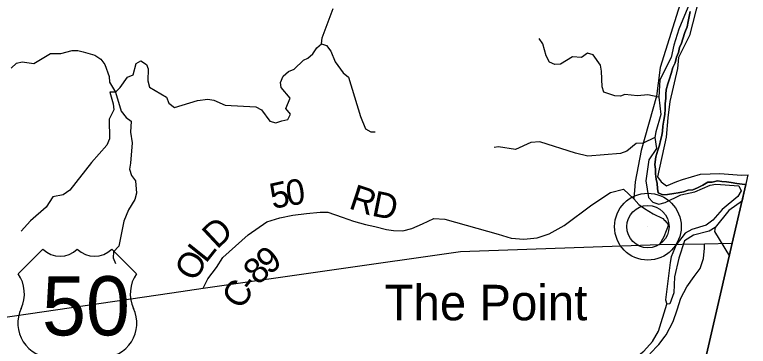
# Model space of a CAD drawing. Extents: x 1525783 to 1900577, y 218250 to 627376.
# Drawn here: x 1720827 to 1729463, y 448212 to 452113 of the extents above; entities that cross this region are included whole.
import ezdxf

# ---------------------------------------------------------------- set-up
doc = ezdxf.new("R2010")
doc.units = 0
for name, color, linetype in [('GM_X_Adjacent_County', 7, 'Continuous'), ('GM_X_County', 7, 'Continuous'), ('GM_X_County_Road', 7, 'Continuous'), ('GM_X_County_Road_Text', 7, 'Continuous'), ('GM_X_Major_Lake', 7, 'Continuous'), ('GM_X_Major_River', 7, 'Continuous'), ('GM_X_Minor_River', 7, 'Continuous'), ('GM_X_Township', 7, 'Continuous'), ('GM_X_Township_Road', 7, 'Continuous'), ('GM_X_Unincorporated', 7, 'Continuous'), ('GM_X_Unincorporated_Location', 7, 'Continuous'), ('GM_X_Unincorporated_Text', 7, 'Continuous'), ('GM_X_US_Location', 7, 'Continuous'), ('GM_X_US_Route', 7, 'Continuous'), ('GM_X_US_Shield', 7, 'Continuous')]:
    doc.layers.add(name, color=color, linetype=linetype)

msp = doc.modelspace()

# ---------------------------------------------------------------- linework, layer by layer
at = {"layer": 'GM_X_Adjacent_County'}
msp.add_lwpolyline([(1727145.2, 440204.4), (1729274, 449424.4), (1729433.6, 450116.2), (1729392, 450119.4), (1729326.2, 450126.4), (1729262.4, 450139.3), (1729206.5, 450146.2), (1729152.6, 450151), (1729098.8, 450159.8), (1729038.5, 450142.6), (1728984.6, 450143.4), (1728926, 450106.1), (1728863.6, 450075), (1728809.3, 450053.7), (1728755.2, 450050.5), (1728701, 450031.2), (1728638.8, 450018.1), (1728584.7, 450008.8), (1728510.5, 449997.9), (1728456.5, 449992.6), (1728402.9, 450017.5), (1728395.7, 450069.7), (1728390.6, 450127.9), (1728377.4, 450180.3), (1728368.3, 450240.5), (1728369.2, 450296.7), (1728362, 450350.9), (1728373.4, 450441), (1728396.6, 450518.8), (1728417.5, 450576.7), (1728430.3, 450632.6), (1728443.2, 450690.6), (1728452.1, 450744.6), (1728457, 450802.7), (1728470, 450872.7), (1728481.1, 450938.7), (1728484, 451002.8), (1728485.1, 451068.9), (1728492, 451127), (1728492.7, 451177.1), (1728497.6, 451231.2), (1728514.6, 451299.1), (1728533.5, 451359), (1728554.5, 451420.8), (1728575.6, 451492.7), (1728602.4, 451548.4), (1728619.4, 451612.3), (1728640.3, 451670.2), (1728653.1, 451726.1), (1728677.9, 451777.9), (1728692.7, 451829.8), (1728715.9, 451905.7), (1728742.9, 451971.5), (1728755.8, 452031.4), (1728766.8, 452093.4), (1728779.7, 452151.4)], dxfattribs=at)
at = {"layer": 'GM_X_County'}
msp.add_lwpolyline([(1728779.7, 452151.4), (1728766.8, 452093.4), (1728755.8, 452031.4), (1728742.9, 451971.5), (1728715.9, 451905.7), (1728692.7, 451829.8), (1728677.9, 451777.9), (1728653.1, 451726.1), (1728640.3, 451670.2), (1728619.4, 451612.3), (1728602.4, 451548.4), (1728575.6, 451492.7), (1728554.5, 451420.8), (1728533.5, 451359), (1728514.6, 451299.1), (1728497.6, 451231.2), (1728492.7, 451177.1), (1728492, 451127), (1728485.1, 451068.9), (1728484, 451002.8), (1728481.1, 450938.7), (1728470, 450872.7), (1728457, 450802.7), (1728452.1, 450744.6), (1728443.2, 450690.6), (1728430.3, 450632.6), (1728417.5, 450576.7), (1728396.6, 450518.8), (1728373.4, 450441), (1728362, 450350.9), (1728369.2, 450296.7), (1728368.3, 450240.5), (1728377.4, 450180.3), (1728390.6, 450127.9), (1728395.7, 450069.7), (1728402.9, 450017.5), (1728456.5, 449992.6), (1728510.5, 449997.9), (1728584.7, 450008.8), (1728638.8, 450018.1), (1728701, 450031.2), (1728755.2, 450050.5), (1728809.3, 450053.7), (1728863.6, 450075), (1728926, 450106.1), (1728984.6, 450143.4), (1729038.5, 450142.6), (1729098.8, 450159.8), (1729152.6, 450151), (1729206.5, 450146.2), (1729262.4, 450139.3), (1729326.2, 450126.4), (1729392, 450119.4), (1729433.6, 450116.2), (1729274, 449424.4), (1727145.2, 440204.4)], dxfattribs=at)
at = {"layer": 'GM_X_County_Road'}
for points in [[(1723046.4, 448894.6), (1723101.1, 449007), (1723204, 449139.7), (1723276.5, 449256.8), (1723576.5, 449524.3), (1723794.1, 449676.9), (1723947.4, 449724.2), (1724102.4, 449755.4), (1724261.2, 449774.5), (1724424, 449789.6), (1724512.3, 449791.9), (1724683.6, 449732.5), (1724817, 449683.8), (1724954.7, 449647.1), (1725066.4, 449620.9), (1725202.1, 449586.2), (1725286.1, 449574.6), (1725394.4, 449570.6), (1725503.1, 449596.6), (1725626.6, 449652.5), (1725762.1, 449714.3), (1725892.4, 449709.8), (1726518.6, 449531.4), (1726672.2, 449486.3), (1726822.3, 449473.5), (1726979, 449486.6), (1727118.3, 449534.2), (1727296.7, 449635.3), (1727620.3, 449878.2), (1727841.8, 450022.7), (1727992.9, 450060), (1728115, 449947.3), (1728173.9, 449881.9), (1728239.1, 449834.5), (1728342.1, 449770.3), (1728457.4, 449715.9), (1728477.8, 449692), (1728478.7, 449691.1)], [(1728478.7, 449691.1), (1728522.1, 449640.3), (1728467.2, 449498.8), (1728418, 449410.4)]]:
    msp.add_lwpolyline(points, dxfattribs=at)
at = {"layer": 'GM_X_Major_Lake'}
msp.add_lwpolyline([(1720787.2, 451484.9), (1720850.2, 451542.3), (1720916.5, 451557.5), (1721052.5, 451539.7), (1721250.6, 451657.6), (1721368.8, 451656.1), (1721503.6, 451692.5), (1721569.7, 451693.7), (1721633.6, 451674.8), (1721769.3, 451637), (1721840.8, 451592), (1721890, 451527.2), (1721938.2, 451388.2), (1721945.2, 451319.9), (1722013.7, 451202.7), (1722070.6, 451256.1), (1722156.5, 451379.4), (1722223, 451404.6), (1722256.9, 451540.6), (1722313.5, 451572), (1722377, 451529), (1722398.3, 451476.6), (1722396.3, 451336.3), (1722415.3, 451261.8), (1722614.1, 451143), (1722643.1, 451072.4), (1722708.6, 451023.4), (1722980.2, 451104.3), (1723100.7, 451120.8), (1723170.7, 451107.9), (1723306.1, 451050), (1723666.6, 451031.4), (1723734.2, 450992.5), (1723830.5, 450860.9), (1723900.3, 450840), (1723970.8, 450863.1), (1724041.2, 450882.3), (1724074.1, 450942), (1724017, 451009), (1724068.8, 451132.7), (1723964.3, 451256.3), (1723955.2, 451316.6), (1723986.2, 451388.4), (1724051.2, 451445.8), (1724115.6, 451471), (1724227.4, 451577.9), (1724277.8, 451601.4), (1724338.6, 451652.8), (1724383.7, 451722.4), (1724438.5, 451771.8), (1724445.5, 451839.9), (1724576.6, 452185.3)], dxfattribs=at)
at = {"layer": 'GM_X_Major_River'}
msp.add_line((1729392.4, 449923.8), (1729462.9, 450229.2), dxfattribs=at)
for points in [[(1728856.8, 452458.2), (1728645.1, 451943.4), (1728584.4, 451753.6), (1728554.3, 451611.6), (1728422.3, 451348.5), (1728409.4, 451142), (1728434.6, 450941.1), (1728375.6, 450735.3), (1728360.6, 450667.3), (1728380.9, 450538.7), (1728290.9, 450407.4), (1728255.3, 450157.1), (1728288.6, 449962.2), (1728339.9, 449907.4), (1728409.7, 449886.4), (1728484.1, 449903.5), (1728667.8, 449995.5), (1728834.6, 450031.5), (1729014, 450109.4), (1729082.3, 450120.6), (1729350.5, 450101.1), (1729377.7, 450040.6), (1729340.7, 449972.9), (1729154.2, 449820.8), (1729044.3, 449697.8), (1728967.3, 449638.6), (1728796.2, 449584.6), (1728719.5, 449541.5), (1728613.3, 449404.4), (1728553.3, 449266.8), (1728542.3, 449198.7), (1728488, 448760.1), (1728503.4, 448708)], [(1728878.6, 452301.5), (1728770.3, 451869.6), (1728640.4, 451608.5), (1728628.6, 451480.2), (1728538.9, 451090.3), (1728514.2, 450900), (1728495, 450671.6), (1728392.2, 450205.6), (1728437.5, 450146.8), (1728500.9, 450099.9), (1728621.9, 450152.5), (1728688.3, 450175.7), (1728901.6, 450237.2), (1729128.2, 450246.4), (1729382.3, 450225.1), (1729462.9, 450229.2)], [(1729392.4, 449923.8), (1729234.2, 449811.8), (1729071.1, 449611.2), (1729002.4, 449568), (1728819.3, 449520.2), (1728710.2, 449451.3), (1728645.2, 449249.6), (1728594, 449031.6), (1728587.4, 448843.1), (1728539.4, 448713.3), (1728503.4, 448708)], [(1727130.7, 447577.8), (1727328.4, 447667.6), (1727408.7, 447676.6), (1727660.9, 447657.4), (1727783.4, 447675.9), (1727846.1, 447719.2), (1727963.1, 447914.3), (1728062.8, 448021.4), (1728231, 448155.6), (1728336.8, 448270.6), (1728404.6, 448390.1), (1728503.4, 448708)]]:
    msp.add_lwpolyline(points, dxfattribs=at)
at = {"layer": 'GM_X_Minor_River'}
msp.add_line((1729392.4, 449923.8), (1729462.9, 450229.2), dxfattribs=at)
for points in [[(1728409.4, 451142), (1728281.6, 451171.8), (1728157.1, 451157.3), (1728009.1, 451173.2), (1727958.7, 451155.8), (1727890.7, 451158.6), (1727761, 451200.4), (1727743.9, 451264.8), (1727734.4, 451447.5), (1727721.4, 451519.8), (1727636.9, 451639.2), (1727569.1, 451662.1), (1727500.2, 451608.9), (1727394.1, 451616.2), (1727252.6, 451529.8), (1727184.5, 451526.6), (1727122.7, 451555.5), (1727081.7, 451630.2), (1727043.6, 451769.1), (1727000.4, 451833.8)], [(1724438.5, 451771.8), (1724498.3, 451749), (1724547.5, 451684.2), (1724597.8, 451559.2), (1724694.2, 451429.7), (1724755.6, 451376.7), (1724897.4, 450915.6), (1724957.5, 450772.5), (1725019.1, 450735.6), (1725069.2, 450735)], [(1722013.7, 451202.7), (1721945.6, 451203.5), (1721987.7, 451066.6), (1721992.7, 450992.3), (1721941.1, 450884.7), (1721943.8, 450652), (1721912.8, 450580.2), (1721729.5, 450375.9), (1721476.4, 450050.1), (1721399.5, 449995), (1721277, 449972.4), (1721199.1, 449849), (1721012.4, 449688.9), (1720904.5, 449567.9)], [(1722013.7, 451202.7), (1722078.7, 450979.2), (1722137.8, 450904.3), (1722197.2, 450859.4), (1722189.5, 450733.1), (1722211.7, 450604.5), (1722190.3, 450366.1), (1722177.3, 450296), (1722202.3, 450223.5), (1722249.5, 450158.7), (1722261.5, 450014.2), (1722242.4, 449940.2), (1722168.6, 449818.8), (1722112.5, 449683.1), (1722052.3, 449391), (1721991.3, 449323.6), (1721986.2, 449251.5), (1722015.4, 449186.9)], [(1728360.6, 450667.3), (1728225.4, 450600.8), (1728141.3, 450599.9), (1728031.8, 450507), (1727957.2, 450479.9), (1727572.1, 450450.6), (1727428.3, 450484.5), (1727007.3, 450616.2), (1726901, 450609.5), (1726723.5, 450529.5), (1726523.6, 450558.1), (1726471.4, 450552.8)], [(1729071.1, 449611.2), (1729064.4, 449563.2), (1729242.3, 449273)], [(1728488, 448760.1), (1728503.4, 448708)], [(1728539.4, 448713.3), (1728503.4, 448708)]]:
    msp.add_lwpolyline(points, dxfattribs=at)
at = {"layer": 'GM_X_Township'}
msp.add_lwpolyline([(1728779.7, 452151.4), (1728766.8, 452093.4), (1728755.8, 452031.4), (1728742.9, 451971.5), (1728715.9, 451905.7), (1728692.7, 451829.8), (1728677.9, 451777.9), (1728653.1, 451726.1), (1728640.3, 451670.2), (1728619.4, 451612.3), (1728602.4, 451548.4), (1728575.6, 451492.7), (1728554.5, 451420.8), (1728533.5, 451359), (1728514.6, 451299.1), (1728497.6, 451231.2), (1728492.7, 451177.1), (1728492, 451127), (1728485.1, 451068.9), (1728484, 451002.8), (1728481.1, 450938.7), (1728470, 450872.7), (1728457, 450802.7), (1728452.1, 450744.6), (1728443.2, 450690.6), (1728430.3, 450632.6), (1728417.5, 450576.7), (1728396.6, 450518.8), (1728373.4, 450441), (1728362, 450350.9), (1728369.2, 450296.7), (1728368.3, 450240.5), (1728377.4, 450180.3), (1728390.6, 450127.9), (1728395.7, 450069.7), (1728402.9, 450017.5), (1728456.5, 449992.6), (1728510.5, 449997.9), (1728584.7, 450008.8), (1728638.8, 450018.1), (1728701, 450031.2), (1728755.2, 450050.5), (1728809.3, 450053.7), (1728863.6, 450075), (1728926, 450106.1), (1728984.6, 450143.4), (1729038.5, 450142.6), (1729098.8, 450159.8), (1729152.6, 450151), (1729206.5, 450146.2), (1729262.4, 450139.3), (1729326.2, 450126.4), (1729392, 450119.4), (1729433.6, 450116.2), (1729274, 449424.4), (1727145.2, 440204.4)], dxfattribs=at)
at = {"layer": 'GM_X_Township_Road'}
for points in [[(1728096.1, 453023.1), (1728096.5, 453023.1), (1728275.5, 453037), (1728439.9, 453037.9), (1728566, 453023.5), (1728700.2, 452912.5), (1728750.7, 452620.4), (1728699.7, 452372.3), (1728423.9, 451491.8), (1728381.2, 451153.2), (1728202.3, 450516), (1728131, 450147.8), (1728115, 449947.3)], [(1728302, 448124.2), (1728408.4, 448232.6), (1728484.2, 448332.8), (1728496.9, 448349.5), (1728580.1, 448504.5), (1728627, 448642.2), (1728669.7, 448778), (1728740.5, 448913.2), (1728825.1, 449034.1), (1728897.1, 449129.2), (1728935.5, 449247), (1728947.9, 449367.2), (1728947.3, 449419.1)]]:
    msp.add_lwpolyline(points, dxfattribs=at)
at = {"layer": 'GM_X_Unincorporated'}
for radius in [392.8, 249]:
    msp.add_circle((1728280.5, 449619.9), radius, dxfattribs=at)
at = {"layer": 'GM_X_Unincorporated_Location'}
msp.add_line((1728280.5, 449619.9), (1728280.5, 449619.9), dxfattribs=at)
at = {"layer": 'GM_X_US_Route'}
for points in [[(1722678.3, 448841.2), (1723046.4, 448894.6), (1726075.7, 449328.9), (1728418, 449410.4), (1728947.3, 449419.1), (1729274, 449424.4)], [(1712725.1, 446219.6), (1712745.9, 446223.8), (1713009.9, 446278.6), (1713151.5, 446331.9), (1714174.1, 446865), (1715097.6, 447363.8), (1715817.9, 447742.4), (1716218.1, 447975), (1716479.5, 448098.1), (1716495.3, 448105.7), (1716619.4, 448165.4), (1716735.1, 448229.3), (1717268.3, 448396.9), (1720312.1, 448497.8), (1722678.3, 448841.2)]]:
    msp.add_lwpolyline(points, dxfattribs=at)
at = {"layer": 'GM_X_US_Shield'}
for p, q in [((1721158.5, 449356.1), (1720868.5, 449066.1)), ((1722260.7, 449066.1), (1721970.7, 449356.1))]:
    msp.add_line(p, q, dxfattribs=at)
for centre, radius, start, end in [((1721361.6, 449563.3), 290, 225.573, 314.427), ((1721767.6, 449563.3), 290, 225.573, 314.427), ((1720535.9, 448833.2), 406.1, 334.54712, 35.00093), ((1722593.3, 448833.2), 406.1, 144.99907, 205.45288), ((1721270, 448486), 406.1, 154.83192, 270.63826), ((1721859.2, 448486), 406.1, 269.36174, 25.16808)]:
    msp.add_arc(centre, radius, start, end, dxfattribs=at)

# ---------------------------------------------------------------- texts
at = {"layer": 'GM_X_County_Road_Text'}
for s, rotation, p in [('5', 12.50002, (1723866.2, 449824.4)), ('0', 7.64657, (1724040, 449863.2)), ('R', 341.79586, (1724747.9, 449837.9)), ('D', 348.6422, (1725019.1, 449751.1)), ('D', 43.15023, (1723209, 449346.8)), ('L', 51.39842, (1723076.7, 449179.8)), ('9', 38.90932, (1723821.9, 449044.7)), ('O', 60.0902, (1722951.9, 448960.9)), ('8', 43.42857, (1723692.4, 448921.8)), ('C', 57.11422, (1723496.2, 448631.3)), ('-', 52.80692, (1723626.6, 448833.3))]:
    msp.add_text(s, height=300, rotation=rotation, dxfattribs=at).set_placement(p)
at = {"layer": 'GM_X_Unincorporated_Text'}
msp.add_text('The Point', height=417, rotation=0.00001, dxfattribs=at).set_placement((1725181.4, 448518.8))
at = {"layer": 'GM_X_US_Location'}
for s in ['0', '/']:
    msp.add_text(s, height=1, dxfattribs=at).set_placement((1721564.3, 448683.6))
msp.add_text('50', height=1, rotation=0.00001, dxfattribs=at).set_placement((1721357.8, 448476.6))
at = {"layer": 'GM_X_US_Shield'}
msp.add_text('50', height=696.1, dxfattribs=at).set_placement((1721148.6, 448341))

doc.saveas('drawing.dxf')
